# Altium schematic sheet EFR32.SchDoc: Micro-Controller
size A4; Organization: Team- Ashwathama; Address1: Colorado Boulder; Address2: Author - Deepesh Sonigra; Address3: Self Checkout Shopping Cart; DocumentNumber: 1; Revision: 1.0; SheetNumber: 5; SheetTotal: 7
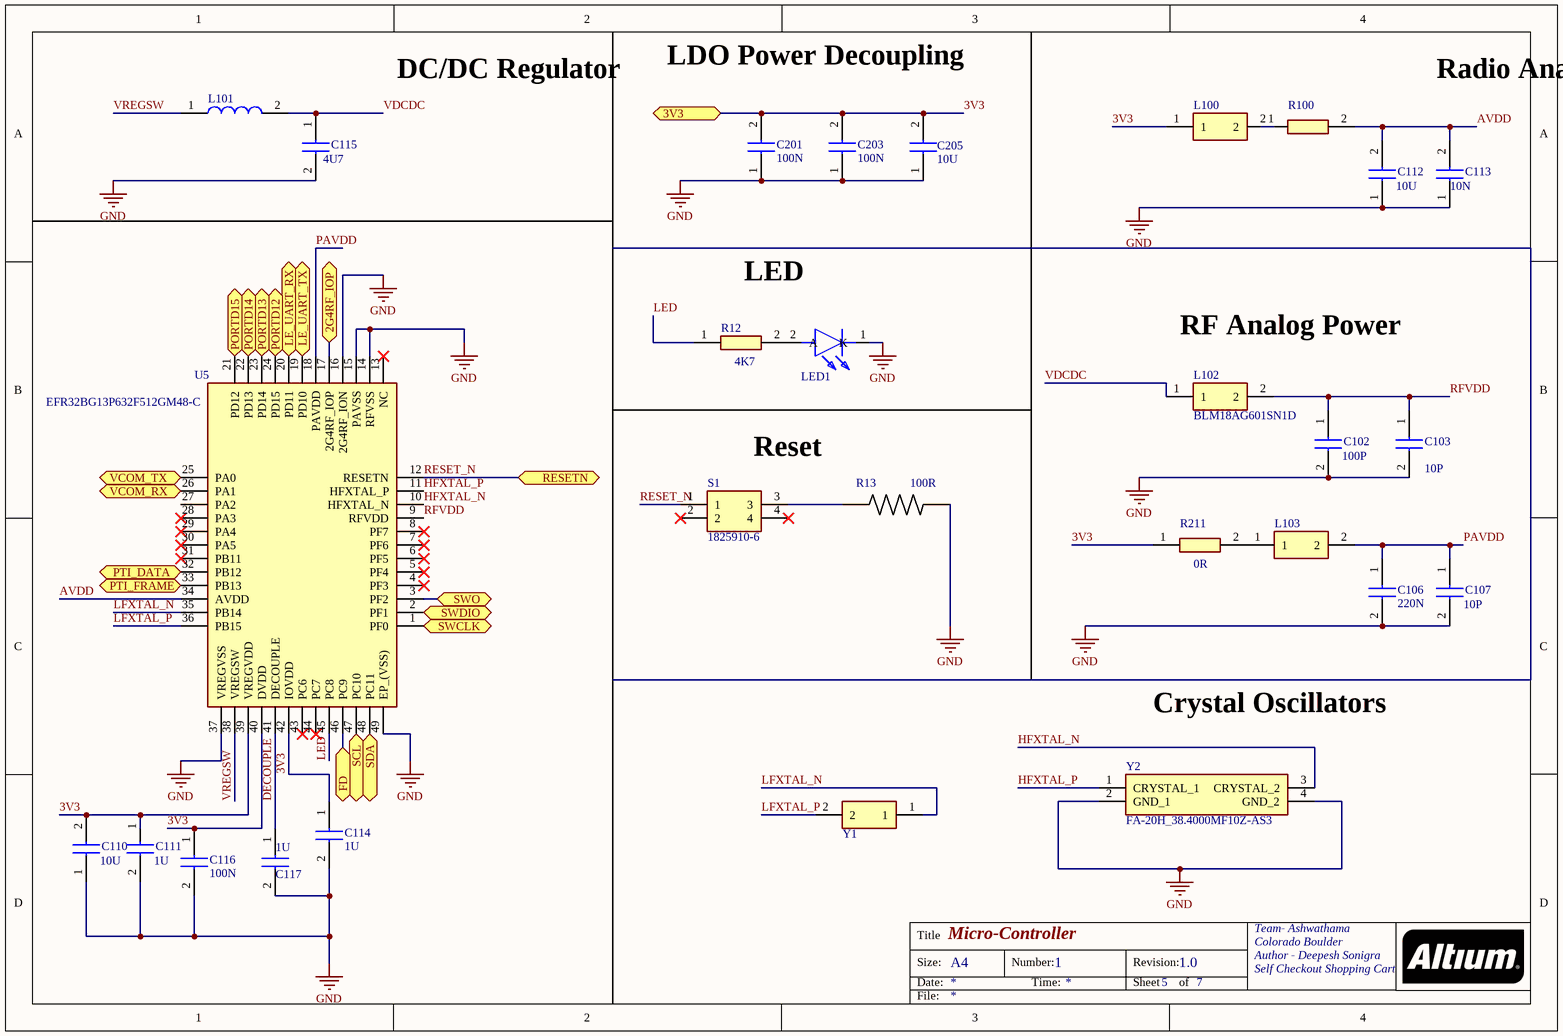
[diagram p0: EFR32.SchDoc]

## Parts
C102  value 100P  [CAPC1608X90N]  (hidden comment: GCM1885C1H101JA16D)
C103  value 10P  [CAPC1608X90N]  (hidden comment: GRM1885C1H100JA01D)
C106  value 220N  [CAPC1608X90N]  (hidden comment: GRM188R71C224KA01D)
C107  value 10P  [CAPC1608X90N]  (hidden comment: GRM1885C1H100JA01D)
C110  value 10U  [CAPC1608X90N]  (hidden comment: GRM188R60J106ME84D)
C111  value 1U  [CAPC1608X90N]  (hidden comment: GRM188R61E105KAADD)
C112  value 10U  [CAPC1608X90N]  (hidden comment: GRM188R60J106ME84D)
C113  value 10N  [CAPC1608X90N]  (hidden comment: CC0603KRX7R7BB103)
C114  value 1U  [CAPC1608X90N]  (hidden comment: GRM188R61E105KAADD)
C115  value 4U7  [CAPC1608X90N]  (hidden comment: GRM188R61E475KE11D)
C116  value 100N  [CAPC1608X90N]  (hidden comment: GCM188R71C104KA37D)
C117  value 1U  [CAPC1608X90N]  (hidden comment: GRM188R61E105KAADD)
C201  value 100N  [CAPC1608X90N]  (hidden comment: GCM188R71C104KA37D)
C203  value 100N  [CAPC1608X90N]  (hidden comment: GCM188R71C104KA37D)
C205  value 10U  [CAPC1608X90N]  (hidden comment: GRM188R61C106KAALJ)
L100  74279266  [BEADC1608X100N]  (value not drawn)
L101  SRN3015-4R7M  [INDPM3027X150N]  (value not drawn)
L102  BLM18AG601SN1D  [BEADC1608X95N]
L103  BLM18AG601SN1D  [BEADC1608X95N]  (value not drawn)
LED1  SML-D12U1WT86  [LEDC1608X65N]  (value not drawn)
R12  value 4K7  [RESC1608X50N]  (hidden comment: RCS06034K70FKEA)
R13  value 100R  [*RESC1608X55N]  (hidden comment: 1-2176326-3)
R100  CRCW02011R00FXED  [RESC0603X28N]  (value not drawn)
R211  value 0R  [RESC0603X28N]  (hidden comment: CRCW02010000Z0ED)
S1  1825910-6  [1825910-6]
U5  EFR32BG13P632F512GM48-C  [*QFN40P600X600X100-49N]
Y1  CM8V-T1A-32.768kHz-12.5pF-20PPM-TA-QC  [CM8V32768TA020125]  (value not drawn)
Y2  FA-20H_38.4000MF10Z-AS3  [FA20H300000MF20XW]

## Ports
2G4RF_IOP, 3V3, FD, LE_UART_RX, LE_UART_TX, PORTD12, PORTD13, PORTD14, PORTD15, PTI_DATA, PTI_FRAME, RESETN, SCL, SDA, SWCLK, SWDIO, SWO, VCOM_RX, VCOM_TX

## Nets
GND: C102.2 C103.2 C106.2 C107.2 C110.1 C111.2 C112.1 C113.1 C114.2 C115.2 C116.2 C117.2 C201.1 C203.1 C205.1 LED1.1(K) R13.2 U5.14(RFVSS) U5.15(PAVSS) U5.16(2G4RF_ION) U5.37(VREGVSS) U5.49(EP_(VSS)) Y2.2(GND_1) Y2.4(GND_2)
2G4RF_IOP: U5.17(2G4RF_IOP) ; port 2G4RF_IOP
3V3: C110.2 C111.1 C114.1 C116.1 C201.2 C203.2 C205.2 L100.1 R211.1 U5.39(VREGVDD) U5.40(DVDD) U5.42(IOVDD) ; port 3V3
AVDD: C112.2 C113.2 R100.2 U5.34(AVDD)
DECOUPLE: C117.1 U5.41(DECOUPLE)
FD: U5.46(PC9) ; port FD
HFXTAL_N: U5.10(HFXTAL_N) Y2.3(CRYSTAL_2)
HFXTAL_P: U5.11(HFXTAL_P) Y2.1(CRYSTAL_1)
LE_UART_RX: U5.20(PD11) ; port LE_UART_RX
LE_UART_TX: U5.19(PD10) ; port LE_UART_TX
LED: R12.1 U5.45(PC8)
LFXTAL_N: U5.35(PB14) Y1.1
LFXTAL_P: U5.36(PB15) Y1.2
PAVDD: C106.1 C107.1 L103.2 U5.18(PAVDD)
PORTD12: U5.24(PD15) ; port PORTD12
PORTD13: U5.23(PD14) ; port PORTD13
PORTD14: U5.22(PD13) ; port PORTD14
PORTD15: U5.21(PD12) ; port PORTD15
PTI_DATA: U5.32(PB12) ; port PTI_DATA
PTI_FRAME: U5.33(PB13) ; port PTI_FRAME
RESET_N: S1.1 U5.12(RESETN) ; port RESETN
RFVDD: C102.1 C103.1 L102.2 U5.9(RFVDD)
SCL: U5.47(PC10) ; port SCL
SDA: U5.48(PC11) ; port SDA
SWCLK: U5.1(PF0) ; port SWCLK
SWDIO: U5.2(PF1) ; port SWDIO
SWO: U5.3(PF2) ; port SWO
VCOM_RX: U5.26(PA1) ; port VCOM_RX
VCOM_TX: U5.25(PA0) ; port VCOM_TX
VDCDC: C115.1 L101.2 L102.1
VREGSW: L101.1 U5.38(VREGSW)
NetL100_2: L100.2 R100.1
NetL103_1: L103.1 R211.2
NetLED1_2: LED1.2(A) R12.2
NetR13_1: R13.1 S1.3

Not connected (* = marked no-connect by the designer): S1 2* 4*; U5 4(PF3)* 5(PF4)* 6(PF5)* 7(PF6)* 8(PF7)* 13(NC)* 27(PA2) 28(PA3)* 29(PA4)* 30(PA5)* 31(PB11)* 43(PC6)* 44(PC7)*

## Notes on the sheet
- (near L101) DC/DC Regulator
- LDO Power Decoupling
- Radio Analog Supply
- LED
- RF Analog Power
- Reset
- Crystal Oscillators

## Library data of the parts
C102 = GCM1885C1H101JA16D: Capacitor; Manufacturer_Name: Murata Electronics
C103 C107 = GRM1885C1H100JA01D: Capacitor; Manufacturer_Name: Murata Electronics
C106 = GRM188R71C224KA01D: Capacitor; Manufacturer_Name: Murata Electronics; Manufacturer_Part_Number: CC0603KPX77BB224
C110 C112 = GRM188R60J106ME84D: Capacitor; Manufacturer_Name: Murata Electronics
C111 C114 C117 = GRM188R61E105KAADD: Capacitor; Manufacturer_Name: Murata Electronics
C113 = CC0603KRX7R7BB103: Capacitor; Manufacturer_Name: YAGEO (PHYCOMP)
C115 = GRM188R61E475KE11D: Capacitor; Manufacturer_Name: Murata Electronics
C116 C201 C203 = GCM188R71C104KA37D: Capacitor; Manufacturer_Name: Murata Electronics
C205 = GRM188R61C106KAALJ: Capacitor; Manufacturer_Name: Murata Electronics
L100 = 74279266: Ferrite Bead; Manufacturer_Name: Wurth Elektronik
L101 = SRN3015-4R7M: Inductor; Manufacturer_Name: Bourns; Allied_Number: 70230754
L102 L103 = BLM18AG601SN1D: Filter; Manufacturer_Name: Murata Electronics
LED1 = SML-D12U1WT86: LED; Manufacturer_Name: ROHM Semiconductor
R12 = RCS06034K70FKEA: Resistor; Manufacturer_Name: Vishay
R13 = CRGP0603F100R: Fixed Resistor CRGP 0603 100R 1%; Manufacturer_Name: TE Connectivity; Detailed Description: 100 Ohms ±1% 0.25W, 1/4W Chip Resistor 0603 (1608 Metric) Pulse Withstanding Thick Film
R100 = CRCW02011R00FXED: Resistor; Manufacturer_Name: Vishay
R211 = CRCW02010000Z0ED: Resistor; Manufacturer_Name: Vishay; Allied_Number: 70202068
S1 = 1825910-6: Switch; Manufacturer_Name: TE Connectivity
U5 = EFR32BG13P632F512GM48-C: Integrated Circuit; Manufacturer_Name: Silicon Labs
Y1 = CM8V-T1A-32.768kHz-12.5pF-20PPM-TA-QC: Crystal or Oscillator; Manufacturer_Name: MICRO CRYSTAL
Y2 = FA-20H_38.4000MF10Z-AS3: Crystal or Oscillator; Manufacturer_Name: Epson Timing; Manufacturer_Part_Number: FA-20H 38.4000MF10Z-AS3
